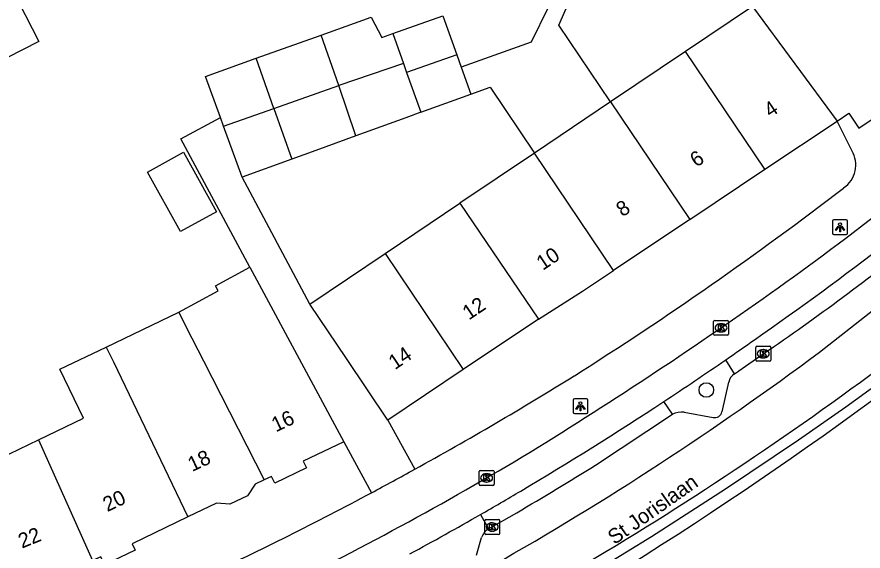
# Model space of a CAD drawing. Extents: x 161801 to 162379, y 382315 to 382832.
# Drawn here: x 162290.6 to 162347.5, y 382522.9 to 382558.9 of the extents above; entities that cross this region are included whole.
import ezdxf

# ---------------------------------------------------------------- set-up
doc = ezdxf.new("R2010")
doc.units = 0
for name, color, linetype in [('IMGEO_Berm_open', 7, 'Continuous'), ('IMGEO_Boom', 7, 'Continuous'), ('IMGEO_Fietspad_open', 7, 'Continuous'), ('IMGEO_Hek', 7, 'Continuous'), ('IMGEO_Kolk', 7, 'Continuous'), ('IMGEO_Lichtpunt', 7, 'Continuous'), ('IMGEO_Openbare_ruimte_label', 7, 'Continuous'), ('IMGEO_Pand', 7, 'Continuous'), ('IMGEO_Pand_nummerreeks', 7, 'Continuous'), ('IMGEO_Parkeervlak_open', 7, 'Continuous'), ('IMGEO_Rijbaan_lokaal_gesloten', 7, 'Continuous'), ('IMGEO_Voetpad_open', 7, 'Continuous')]:
    doc.layers.add(name, color=color, linetype=linetype)

msp = doc.modelspace()

# ---------------------------------------------------------------- linework, layer by layer
at = {"layer": 'IMGEO_Berm_open'}
for points in [[(162338.822, 382534.867), (162338.241, 382535.811)], [(162334.655, 382532.146), (162334.076, 382532.999)], [(162321.75, 382525.399), (162322.289, 382524.445)]]:
    msp.add_lwpolyline(points, dxfattribs=at)
at = {"layer": 'IMGEO_Boom'}
msp.add_circle((162336.934, 382533.777), 0.489, dxfattribs=at)
at = {"layer": 'IMGEO_Fietspad_open'}
for centre, radius, start, end in [((162204.706, 382731.847), 235.243, 305.63531, 308.07241), ((162211.901, 382721.311), 224.423, 304.85879, 307.69437), ((162166.031, 382787.471), 302.985, 301.66709, 305.45092), ((162215.164, 382714.214), 216.739, 304.60116, 305.22334), ((162203.482, 382730.919), 237.123, 303.4181, 304.63241), ((162204.361, 382729.537), 235.484, 300.6663, 303.42482), ((162210.896, 382719.34), 221.458, 295.84931, 301.04157), ((162202.021, 382733.76), 240.311, 299.88276, 300.63273), ((162212.702, 382715.356), 219.032, 298.43923, 299.85868)]:
    msp.add_arc(centre, radius, start, end, dxfattribs=at)
at = {"layer": 'IMGEO_Hek'}
msp.add_lwpolyline([(162363.387, 382545.959), (162359.247, 382542.465), (162355.008, 382539.089), (162350.695, 382535.807), (162346.31, 382532.621), (162343.129, 382530.401), (162338.224, 382527.103), (162333.252, 382523.906), (162328.217, 382520.81), (162323.12, 382517.817), (162321.628, 382516.967)], dxfattribs=at)
at = {"layer": 'IMGEO_Kolk'}
for p, q in [((162337.42, 382537.531), (162337.42, 382538.383)), ((162337.495, 382538.457), (162338.347, 382538.457)), ((162337.908, 382538.237), (162337.933, 382538.237)), ((162338.421, 382538.383), (162338.421, 382537.531)), ((162337.931, 382537.677), (162337.906, 382537.677)), ((162338.347, 382537.457), (162337.495, 382537.457)), ((162340.257, 382535.788), (162340.257, 382536.64)), ((162340.332, 382536.714), (162341.184, 382536.714)), ((162340.745, 382536.494), (162340.77, 382536.494)), ((162341.258, 382536.64), (162341.258, 382535.788)), ((162340.768, 382535.934), (162340.743, 382535.934)), ((162341.184, 382535.714), (162340.332, 382535.714)), ((162321.668, 382527.439), (162321.668, 382528.291)), ((162321.743, 382528.365), (162322.595, 382528.365)), ((162322.156, 382528.145), (162322.181, 382528.145)), ((162322.669, 382528.291), (162322.669, 382527.439)), ((162322.595, 382527.365), (162321.743, 382527.365)), ((162322.179, 382527.585), (162322.154, 382527.585)), ((162322.045, 382524.138), (162322.045, 382524.99)), ((162322.12, 382525.064), (162322.972, 382525.064)), ((162323.046, 382524.99), (162323.046, 382524.138)), ((162322.533, 382524.844), (162322.558, 382524.844)), ((162322.972, 382524.064), (162322.12, 382524.064)), ((162322.556, 382524.284), (162322.531, 382524.284))]:
    msp.add_line(p, q, dxfattribs=at)
for points in [[(162337.42, 382537.531), (162337.42, 382538.383)], [(162337.495, 382538.457), (162338.347, 382538.457)], [(162337.741, 382538.157), (162337.864, 382538.157), (162337.864, 382538.006), (162337.994, 382538.157), (162338.158, 382538.157), (162338.012, 382538.006), (162338.165, 382537.757), (162338.013, 382537.757), (162337.928, 382537.921), (162337.864, 382537.854), (162337.864, 382537.757), (162337.741, 382537.757), (162337.741, 382538.157)], [(162338.421, 382538.383), (162338.421, 382537.531)], [(162338.347, 382537.457), (162337.495, 382537.457)], [(162340.257, 382535.788), (162340.257, 382536.64)], [(162340.332, 382536.714), (162341.184, 382536.714)], [(162340.578, 382536.414), (162340.701, 382536.414), (162340.701, 382536.263), (162340.831, 382536.414), (162340.995, 382536.414), (162340.849, 382536.263), (162341.002, 382536.014), (162340.85, 382536.014), (162340.765, 382536.178), (162340.701, 382536.111), (162340.701, 382536.014), (162340.578, 382536.014), (162340.578, 382536.414)], [(162341.258, 382536.64), (162341.258, 382535.788)], [(162341.184, 382535.714), (162340.332, 382535.714)], [(162321.668, 382527.439), (162321.668, 382528.291)], [(162321.743, 382528.365), (162322.595, 382528.365)], [(162321.989, 382528.065), (162322.112, 382528.065), (162322.112, 382527.914), (162322.242, 382528.065), (162322.406, 382528.065), (162322.26, 382527.914), (162322.413, 382527.665), (162322.261, 382527.665), (162322.176, 382527.829), (162322.112, 382527.762), (162322.112, 382527.665), (162321.989, 382527.665), (162321.989, 382528.065)], [(162322.669, 382528.291), (162322.669, 382527.439)], [(162322.595, 382527.365), (162321.743, 382527.365)], [(162322.045, 382524.138), (162322.045, 382524.99)], [(162322.12, 382525.064), (162322.972, 382525.064)], [(162323.046, 382524.99), (162323.046, 382524.138)], [(162322.366, 382524.764), (162322.489, 382524.764), (162322.489, 382524.613), (162322.619, 382524.764), (162322.783, 382524.764), (162322.637, 382524.613), (162322.79, 382524.364), (162322.638, 382524.364), (162322.553, 382524.528), (162322.489, 382524.461), (162322.489, 382524.364), (162322.366, 382524.364), (162322.366, 382524.764)], [(162322.972, 382524.064), (162322.12, 382524.064)]]:
    msp.add_lwpolyline(points, dxfattribs=at)
for centre, start, end in [((162337.497, 382538.381), 91.552, 178.448), ((162337.497, 382538.381), 91.552, 178.448), ((162338.345, 382538.381), 1.552, 88.448), ((162338.345, 382538.381), 1.552, 88.448), ((162337.497, 382537.533), 181.552, 268.448), ((162337.497, 382537.533), 181.552, 268.448), ((162338.345, 382537.533), 271.552, 358.448), ((162338.345, 382537.533), 271.552, 358.448), ((162340.334, 382536.638), 91.552, 178.448), ((162340.334, 382536.638), 91.552, 178.448), ((162341.182, 382536.638), 1.552, 88.448), ((162341.182, 382536.638), 1.552, 88.448), ((162340.334, 382535.79), 181.552, 268.448), ((162340.334, 382535.79), 181.552, 268.448), ((162341.182, 382535.79), 271.552, 358.448), ((162341.182, 382535.79), 271.552, 358.448), ((162321.745, 382528.289), 91.552, 178.448), ((162321.745, 382528.289), 91.552, 178.448), ((162322.593, 382528.289), 1.552, 88.448), ((162322.593, 382528.289), 1.552, 88.448), ((162321.745, 382527.441), 181.552, 268.448), ((162321.745, 382527.441), 181.552, 268.448), ((162322.593, 382527.441), 271.552, 358.448), ((162322.593, 382527.441), 271.552, 358.448), ((162322.122, 382524.988), 91.552, 178.448), ((162322.122, 382524.988), 91.552, 178.448), ((162322.97, 382524.988), 1.552, 88.448), ((162322.97, 382524.988), 1.552, 88.448), ((162322.122, 382524.14), 181.552, 268.448), ((162322.122, 382524.14), 181.552, 268.448), ((162322.97, 382524.14), 271.552, 358.448), ((162322.97, 382524.14), 271.552, 358.448)]:
    msp.add_arc(centre, 0.0765, start, end, dxfattribs=at)
for centre, major_axis, ratio, start_param, end_param in [((162337.907, 382537.957), (-0.387, 0.002), 0.722429, 4.712389, 7.853982), ((162337.932, 382537.957), (-0.39, 0.002), 0.717154, 1.570796, 4.712389), ((162340.744, 382536.214), (-0.387, 0.002), 0.722429, 4.712389, 7.853982), ((162340.769, 382536.214), (-0.39, 0.002), 0.717154, 1.570796, 4.712389), ((162322.155, 382527.865), (-0.387, 0.002), 0.722429, 4.712389, 7.853982), ((162322.18, 382527.865), (-0.39, 0.002), 0.717154, 1.570796, 4.712389), ((162322.532, 382524.564), (-0.387, 0.002), 0.722429, 4.712389, 7.853982), ((162322.557, 382524.564), (-0.39, 0.002), 0.717154, 1.570796, 4.712389)]:
    msp.add_ellipse(centre, major_axis=major_axis, ratio=ratio, start_param=start_param, end_param=end_param, dxfattribs=at)
at = {"layer": 'IMGEO_Lichtpunt'}
for p, q in [((162345.416, 382545.128), (162345.416, 382544.321)), ((162345.416, 382545.128), (162345.416, 382544.321)), ((162346.318, 382545.223), (162345.51, 382545.223)), ((162346.318, 382545.223), (162345.51, 382545.223)), ((162346.412, 382544.321), (162346.412, 382545.128)), ((162346.412, 382544.321), (162346.412, 382545.128)), ((162345.51, 382544.227), (162346.318, 382544.227)), ((162345.51, 382544.227), (162346.318, 382544.227)), ((162327.975, 382533.091), (162327.975, 382532.284)), ((162327.975, 382533.091), (162327.975, 382532.284)), ((162328.877, 382533.186), (162328.069, 382533.186)), ((162328.877, 382533.186), (162328.069, 382533.186)), ((162328.971, 382532.284), (162328.971, 382533.091)), ((162328.971, 382532.284), (162328.971, 382533.091)), ((162328.069, 382532.19), (162328.877, 382532.19)), ((162328.069, 382532.19), (162328.877, 382532.19))]:
    msp.add_line(p, q, dxfattribs=at)
for points in [[(162345.79, 382544.792), (162345.829, 382544.764), (162345.641, 382544.502), (162345.603, 382544.529), (162345.79, 382544.792)], [(162345.892, 382544.744), (162345.939, 382544.744), (162345.939, 382544.422), (162345.892, 382544.422), (162345.892, 382544.744)], [(162346.002, 382544.764), (162346.04, 382544.791), (162346.227, 382544.529), (162346.188, 382544.501), (162346.002, 382544.764)], [(162328.349, 382532.755), (162328.388, 382532.727), (162328.2, 382532.465), (162328.162, 382532.492), (162328.349, 382532.755)], [(162328.451, 382532.707), (162328.498, 382532.707), (162328.498, 382532.385), (162328.451, 382532.385), (162328.451, 382532.707)], [(162328.561, 382532.727), (162328.599, 382532.754), (162328.786, 382532.492), (162328.747, 382532.464), (162328.561, 382532.727)]]:
    msp.add_lwpolyline(points, dxfattribs=at)
for centre in [(162345.915, 382544.926), (162328.474, 382532.889)]:
    msp.add_circle(centre, 0.0994, dxfattribs=at)
for centre, start, end in [((162345.51, 382545.128), 90, 180), ((162345.51, 382545.128), 90, 180), ((162346.318, 382545.128), 0, 90), ((162346.318, 382545.128), 0, 90), ((162345.51, 382544.321), 180, 270), ((162345.51, 382544.321), 180, 270), ((162346.318, 382544.321), 270, 0), ((162346.318, 382544.321), 270, 360), ((162328.069, 382533.091), 90, 180), ((162328.069, 382533.091), 90, 180), ((162328.877, 382533.091), 0, 90), ((162328.877, 382533.091), 0, 90), ((162328.069, 382532.284), 180, 270), ((162328.069, 382532.284), 180, 270), ((162328.877, 382532.284), 270, 0), ((162328.877, 382532.284), 270, 360)]:
    msp.add_arc(centre, 0.0946, start, end, dxfattribs=at)
at = {"layer": 'IMGEO_Pand'}
for points in [[(162287.792, 382555.026), (162285.977, 382558.59), (162290.263, 382560.773), (162292.079, 382557.208), (162287.792, 382555.026)], [(162340.045, 382559.569), (162335.543, 382556.541)], [(162340.045, 382559.569), (162345.715, 382551.865)], [(162311.043, 382557.637), (162314.413, 382558.84), (162315.139, 382557.477), (162315.871, 382557.739)], [(162315.871, 382557.739), (162319.233, 382558.939), (162320.174, 382556.31)], [(162306.686, 382556.083), (162311.043, 382557.637)], [(162312.242, 382554.253), (162311.043, 382557.637)], [(162315.871, 382557.739), (162316.578, 382555.74)], [(162320.174, 382556.31), (162316.792, 382555.133)], [(162320.174, 382556.31), (162320.47, 382555.482)], [(162335.543, 382556.541), (162330.495, 382553.145)], [(162340.868, 382548.619), (162335.543, 382556.541)], [(162304.277, 382552.099), (162303.271, 382554.864), (162306.686, 382556.083)], [(162307.882, 382552.709), (162306.686, 382556.083)], [(162316.578, 382555.74), (162312.242, 382554.253)], [(162316.578, 382555.74), (162316.792, 382555.133)], [(162316.792, 382555.133), (162317.74, 382552.451)], [(162320.47, 382555.482), (162321.115, 382553.679)], [(162307.882, 382552.709), (162312.242, 382554.253)], [(162313.382, 382550.865), (162312.242, 382554.253)], [(162345.715, 382551.865), (162346.501, 382552.392), (162347.178, 382551.384), (162351.407, 382554.224)], [(162317.74, 382552.451), (162321.115, 382553.679)], [(162330.495, 382553.145), (162325.379, 382549.704)], [(162330.495, 382553.145), (162335.814, 382545.234)], [(162304.492, 382551.509), (162307.882, 382552.709)], [(162307.882, 382552.709), (162309.088, 382549.303)], [(162317.74, 382552.451), (162316.741, 382552.088), (162313.382, 382550.865)], [(162304.492, 382551.509), (162304.277, 382552.099)], [(162340.868, 382548.619), (162345.715, 382551.865)], [(162305.738, 382548.084), (162304.492, 382551.509)], [(162313.382, 382550.865), (162310.687, 382549.885), (162309.088, 382549.303)], [(162299.385, 382548.426), (162301.8, 382549.769), (162304.025, 382545.767), (162301.61, 382544.425), (162299.385, 382548.426)], [(162325.379, 382549.704), (162320.376, 382546.339)], [(162330.692, 382541.802), (162325.379, 382549.704)], [(162309.088, 382549.303), (162305.738, 382548.084)], [(162335.814, 382545.234), (162340.868, 382548.619)], [(162315.346, 382542.955), (162320.376, 382546.339)], [(162320.376, 382546.339), (162325.649, 382538.55)], [(162335.814, 382545.234), (162330.692, 382541.802)], [(162310.295, 382539.557), (162315.346, 382542.955)], [(162315.346, 382542.955), (162320.592, 382535.151)], [(162301.486, 382539.008), (162304.142, 382540.434), (162303.953, 382540.788), (162306.267, 382542.03)], [(162306.267, 382542.03), (162310.201, 382534.699), (162312.565, 382530.293)], [(162325.649, 382538.55), (162328.616, 382540.412), (162330.692, 382541.802)], [(162315.54, 382531.754), (162312.751, 382535.904), (162310.295, 382539.557)], [(162296.602, 382536.668), (162301.486, 382539.008)], [(162301.486, 382539.008), (162301.991, 382538.01), (162303.138, 382535.744), (162307.223, 382527.729)], [(162325.649, 382538.55), (162320.592, 382535.151)], [(162292.064, 382530.429), (162295.088, 382531.885), (162293.499, 382535.175), (162296.602, 382536.668)], [(162296.602, 382536.668), (162297.096, 382535.665), (162302.098, 382525.243)], [(162320.592, 382535.151), (162315.54, 382531.754)], [(162284.621, 382531.692), (162286.967, 382532.667), (162288.678, 382529.104), (162288.797, 382528.857), (162292.064, 382530.429)], [(162292.064, 382530.429), (162295.69, 382522.304)], [(162312.565, 382530.293), (162309.842, 382528.985), (162310.056, 382528.539), (162307.938, 382527.522), (162307.723, 382527.969), (162307.223, 382527.729)], [(162307.223, 382527.729), (162306.628, 382527.443), (162306.099, 382526.669), (162304.907, 382526.097), (162304.017, 382526.164), (162302.098, 382525.243)], [(162302.098, 382525.243), (162298.349, 382523.442), (162298.553, 382523.017), (162296.494, 382522.029), (162296.236, 382522.566), (162295.69, 382522.304)]]:
    msp.add_lwpolyline(points, dxfattribs=at)
at = {"layer": 'IMGEO_Parkeervlak_open'}
for points in [[(162338.822, 382534.867), (162339.1, 382535.053), (162339.125, 382535.07), (162340.759, 382536.213)], [(162337.986, 382532.314), (162338.439, 382534.293)], [(162329.492, 382528.731), (162334.655, 382532.146)], [(162335.439, 382532.28), (162337.383, 382531.936)], [(162322.289, 382524.445), (162324.193, 382525.522)], [(162321.497, 382522.673), (162321.823, 382523.856)]]:
    msp.add_lwpolyline(points, dxfattribs=at)
for centre, radius, start, end in [((162243.031, 382679.281), 173.261, 304.33631, 308.67696), ((162339.244, 382534.171), 0.814, 121.2227, 171.3511), ((162335.259, 382530.975), 1.317, 82.1302, 117.2681), ((162337.496, 382532.425), 0.502, 256.9834, 347.181), ((162204.773, 382728.699), 235.673, 300.44545, 301.95157), ((162323.008, 382523.397), 1.271, 124.4622, 158.8378)]:
    msp.add_arc(centre, radius, start, end, dxfattribs=at)
at = {"layer": 'IMGEO_Rijbaan_lokaal_gesloten'}
msp.add_lwpolyline([(162344.527, 382536.322), (162355.383, 382544.828)], dxfattribs=at)
for centre, radius, start, end in [((162209.917, 382721.917), 232.524, 298.41717, 310.89166), ((162187.459, 382752.01), 271.525, 301.54016, 310.38113), ((162221.277, 382700.985), 205.68, 299.50803, 306.8148)]:
    msp.add_arc(centre, radius, start, end, dxfattribs=at)
at = {"layer": 'IMGEO_Voetpad_open'}
for points in [[(162330.495, 382553.145), (162327.021, 382558.312), (162328.388, 382561.458)], [(162326.31, 382559.507), (162325.171, 382557.164), (162320.47, 382555.482)], [(162321.115, 382553.679), (162322.401, 382554.133), (162325.379, 382549.704)], [(162306.267, 382542.03), (162301.633, 382550.675), (162304.277, 382552.099)], [(162346.72, 382549.876), (162345.715, 382551.865)], [(162310.295, 382539.557), (162305.738, 382548.084)], [(162315.54, 382531.754), (162317.337, 382528.447)], [(162312.565, 382530.293), (162314.427, 382526.864)]]:
    msp.add_lwpolyline(points, dxfattribs=at)
for centre, radius, start, end in [((162345.062, 382548.926), 1.911, 305.0043, 29.8127), ((162200.083, 382737.525), 239.794, 302.25653, 307.52964), ((162201.49, 382738.187), 239.607, 298.91335, 301.88739), ((162199.222, 382742.109), 244.136, 298.15685, 298.93431), ((162201.544, 382737.948), 239.372, 295.13208, 298.13684)]:
    msp.add_arc(centre, radius, start, end, dxfattribs=at)

# ---------------------------------------------------------------- texts
at = {"layer": 'IMGEO_Openbare_ruimte_label'}
msp.add_text('St Jorislaan', height=1, rotation=35.1047, dxfattribs=at).set_placement((162330.756, 382523.34))
at = {"layer": 'IMGEO_Pand_nummerreeks'}
for s, rotation, p in [('4', 33.9134, (162341.232, 382552.062)), ('6', 33.9134, (162336.264, 382548.722)), ('8', 33.9134, (162331.298, 382545.385)), ('10', 33.9134, (162325.946, 382541.787)), ('12', 33.9122, (162320.974, 382538.444)), ('14', 33.9122, (162316.008, 382535.106)), ('16', 25.3362, (162308.01, 382530.924)), ('18', 25.3362, (162302.386, 382528.261)), ('20', 25.3341, (162296.679, 382525.56)), ('22', 21.959, (162290.947, 382523.108))]:
    msp.add_text(s, height=1, rotation=rotation, dxfattribs=at).set_placement(p)

doc.saveas('drawing.dxf')
